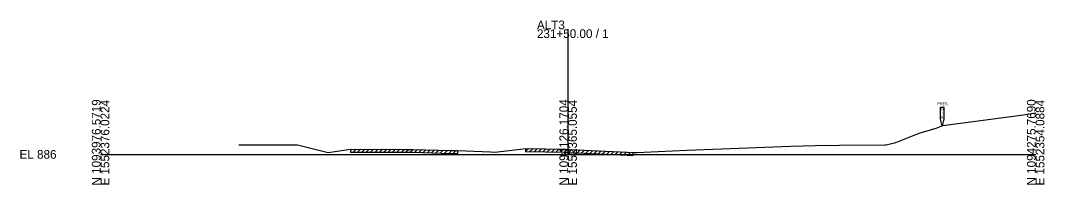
# Model space of a CAD drawing. Extents: x -26 to 1303, y -10 to 19582.
# Drawn here: x -25.7 to 302.8, y 4990.3 to 5043 of the extents above; entities that cross this region are included whole.
import ezdxf

# ---------------------------------------------------------------- set-up
doc = ezdxf.new("R2010")
doc.units = 0
for name, color, linetype in [('Default', 7, 'Continuous'), ('RD_GPK_XS_Cell', 7, 'Continuous'), ('RD_XS_ExGround', 7, 'Continuous'), ('RD_XS_ExPaveRet', 7, 'Continuous'), ('RD_XS_ExRW', 7, 'Continuous'), ('RD_XS_TX_Elev_EX', 7, 'Continuous')]:
    doc.layers.add(name, color=color, linetype=linetype)

msp = doc.modelspace()

# ---------------------------------------------------------------- linework, layer by layer
at = {"layer": 'RD_GPK_XS_Cell'}
for p, q in [((150, 5000), (150, 5040.19)), ((0, 5000), (150, 5000)), ((150, 5000), (300, 5000))]:
    msp.add_line(p, q, dxfattribs=at)
at = {"layer": 'RD_XS_ExGround'}
msp.add_lwpolyline([(44.34, 5003.05), (55.09, 5003.07), (63.23, 5003.08), (70.93, 5001.13), (73.05, 5000.63), (78.79, 5001.48), (80.15, 5001.7), (96.75, 5001.62), (100.29, 5001.61), (112.3, 5001.26), (114.52, 5001.2), (125.12, 5000.82), (126.54, 5000.75), (134.68, 5001.72), (136.29, 5001.87), (148.91, 5001.63), (150, 5001.61), (150.54, 5001.6), (168.93, 5000.69), (170.74, 5000.61), (171.63, 5000.58), (172.17, 5000.63), (174.31, 5000.71), (188.11, 5001.35), (221.42, 5002.65), (233.23, 5002.99), (234.5, 5002.87), (237.03, 5002.99), (251.56, 5003.03), (252.02, 5003.08), (255.14, 5003.79), (262.65, 5006.84), (268.13, 5008.38), (270.21, 5009.25), (296.07, 5012.71), (300, 5013.4)], dxfattribs=at)
at = {"layer": 'RD_XS_ExPaveRet'}
for p, q in [((80.15, 5001.7), (80.15, 5000.7)), ((80.15, 5001.29), (80.56, 5001.7)), ((81.02, 5000.75), (81.97, 5001.69)), ((82.43, 5000.74), (83.38, 5001.69)), ((83.84, 5000.73), (84.78, 5001.68)), ((85.25, 5000.73), (86.19, 5001.67)), ((86.65, 5000.72), (87.6, 5001.67)), ((88.06, 5000.71), (89.01, 5001.66)), ((89.47, 5000.71), (90.41, 5001.65)), ((90.88, 5000.7), (91.82, 5001.65)), ((92.28, 5000.69), (93.23, 5001.64)), ((93.69, 5000.69), (94.64, 5001.63)), ((95.1, 5000.68), (96.04, 5001.63)), ((96.51, 5000.67), (97.45, 5001.62)), ((97.91, 5000.67), (98.86, 5001.61)), ((99.32, 5000.66), (100.27, 5001.61)), ((100.72, 5000.64), (101.64, 5001.57)), ((102.09, 5000.61), (103.02, 5001.53)), ((103.47, 5000.57), (104.39, 5001.49)), ((104.84, 5000.53), (105.77, 5001.45)), ((106.22, 5000.49), (107.14, 5001.41)), ((107.59, 5000.45), (108.52, 5001.37)), ((108.97, 5000.41), (109.89, 5001.33)), ((110.34, 5000.37), (111.27, 5001.29)), ((111.72, 5000.33), (112.64, 5001.25)), ((113.09, 5000.29), (114.02, 5001.21)), ((114.47, 5000.25), (114.52, 5000.3)), ((114.52, 5001.2), (114.52, 5000.2)), ((136.29, 5001.87), (136.29, 5000.87)), ((136.38, 5000.92), (137.31, 5001.85)), ((137.77, 5000.89), (138.7, 5001.82)), ((139.15, 5000.86), (140.09, 5001.8)), ((140.54, 5000.84), (141.47, 5001.77)), ((141.93, 5000.81), (142.86, 5001.74)), ((143.32, 5000.78), (144.25, 5001.72)), ((144.7, 5000.76), (145.64, 5001.69)), ((146.09, 5000.73), (147.02, 5001.66)), ((147.48, 5000.7), (148.41, 5001.64)), ((148.87, 5000.68), (149.8, 5001.61)), ((150.26, 5000.65), (151.17, 5001.57)), ((151.61, 5000.6), (152.52, 5001.5)), ((152.96, 5000.53), (153.87, 5001.43)), ((154.31, 5000.46), (155.22, 5001.37)), ((155.66, 5000.4), (156.56, 5001.3)), ((157.01, 5000.33), (157.91, 5001.24)), ((158.35, 5000.26), (159.26, 5001.17)), ((159.7, 5000.2), (160.61, 5001.1)), ((161.05, 5000.13), (161.96, 5001.04)), ((162.4, 5000.06), (163.3, 5000.97)), ((163.75, 5000), (164.65, 5000.9)), ((165.09, 4999.93), (166, 5000.84)), ((166.44, 4999.87), (167.35, 5000.77)), ((167.79, 4999.8), (168.7, 5000.71)), ((169.14, 4999.73), (170.05, 5000.64)), ((170.74, 5000.61), (170.74, 4999.61)), ((170.49, 4999.67), (170.74, 4999.92))]:
    msp.add_line(p, q, dxfattribs=at)
for points in [[(80.15, 5000.75), (96.73, 5000.67), (100.29, 5000.66), (112.28, 5000.31), (114.52, 5000.25)], [(136.29, 5000.92), (148.9, 5000.68), (150, 5000.66), (150.54, 5000.65), (168.91, 4999.74), (170.74, 4999.66)]]:
    msp.add_lwpolyline(points, dxfattribs=at)
at = {"layer": 'RD_XS_ExRW'}
msp.add_lwpolyline([(269.45, 5015.18), (270.55, 5015.18), (270.55, 5011.35), (270, 5009.17), (269.45, 5011.35)], close=True, dxfattribs=at)

# ---------------------------------------------------------------- texts
at = {"layer": 'Default'}
msp.add_text('-', height=0.0001, dxfattribs=at).set_placement((0, 5000))
at = {"layer": 'RD_GPK_XS_Cell'}
for s, p in [('ALT3', (140, 5040.19)), ('231+50.00 / 1', (140, 5037.39)), ('EL 886', (-26, 4998.6))]:
    msp.add_text(s, height=2.8, dxfattribs=at).set_placement(p)
for s, p in [('N 1093976.5719', (0, 4990)), ('E 1552376.0224', (2.8, 4990)), ('N 1094126.1704', (150, 4990)), ('E 1552365.0554', (152.8, 4990)), ('N 1094275.7690', (300, 4990)), ('E 1552354.0884', (302.8, 4990))]:
    msp.add_text(s, height=2.8, rotation=90, dxfattribs=at).set_placement(p)
at = {"layer": 'RD_XS_ExRW'}
for s, p in [('PRES.', (268.45, 5015.81)), ('R', (269.71, 5014.09)), ('/', (269.83, 5012.78)), ('W', (269.53, 5011.47))]:
    msp.add_text(s, height=0.875, dxfattribs=at).set_placement(p)
at = {"layer": 'RD_XS_TX_Elev_EX'}
msp.add_text('887.61', height=1.25, dxfattribs=at).set_placement((147.56, 4999.18))

doc.saveas('drawing.dxf')
